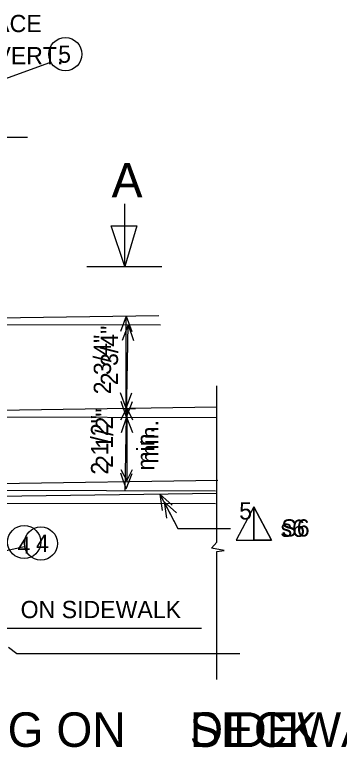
# Model space of a CAD drawing. Extents: x 1509.2 to 1521.3, y 1506 to 1514.6.
# Drawn here: x 1511.957 to 1512.741, y 1509.298 to 1511.067 of the extents above; entities that cross this region are included whole.
import ezdxf

# ---------------------------------------------------------------- set-up
doc = ezdxf.new("R2010")
doc.units = 0
for name, color, linetype in [('Level 2', 7, 'Continuous'), ('Level 3', 7, 'Continuous'), ('Level 4', 7, 'Continuous'), ('Level 60', 7, 'Continuous')]:
    doc.layers.add(name, color=color, linetype=linetype)

msp = doc.modelspace()

# ---------------------------------------------------------------- linework, layer by layer
at = {"layer": 'Level 2'}
msp.add_line((1512.5343, 1509.8786), (1512.5343, 1509.7983), dxfattribs=at)
for points in [[(1512.4919, 1509.7983), (1512.5767, 1509.7983), (1512.5343, 1509.8786)], [(1512.5343, 1509.8786), (1512.5767, 1509.7983), (1512.5343, 1509.7983)]]:
    msp.add_lwpolyline(points, close=True, dxfattribs=at)
at = {"layer": 'Level 3'}
for p, q in [((1512.2236, 1510.4586), (1512.2236, 1510.6102)), ((1512.2236, 1510.4586), (1512.1906, 1510.5574)), ((1512.1906, 1510.5574), (1512.2523, 1510.5574)), ((1512.2523, 1510.5574), (1512.2236, 1510.4586)), ((1512.1313, 1510.4586), (1512.3125, 1510.4586)), ((1511.7425, 1510.3321), (1512.3049, 1510.3405)), ((1512.2268, 1510.3393), (1512.2131, 1510.3018)), ((1512.2268, 1510.3393), (1512.2131, 1510.3018)), ((1512.2268, 1510.1165), (1512.2268, 1510.3393)), ((1512.2268, 1510.3393), (1512.2404, 1510.3018)), ((1512.2268, 1510.3393), (1512.2404, 1510.3018)), ((1512.4451, 1509.7934), (1512.4451, 1510.1704)), ((1512.2268, 1510.1165), (1512.2131, 1510.1541)), ((1512.2268, 1510.1165), (1512.2404, 1510.1541)), ((1510.9693, 1510.0976), (1512.445, 1510.1198)), ((1512.2186, 1510.1157), (1512.2486, 1510.1157)), ((1512.2278, 1510.1165), (1512.2278, 1509.9395)), ((1511.0337, 1509.9216), (1512.4477, 1509.9428)), ((1511.0322, 1509.8914), (1512.445, 1509.9114)), ((1512.308, 1509.9093), (1512.3512, 1509.826)), ((1512.308, 1509.9093), (1512.3132, 1509.8697)), ((1512.308, 1509.9093), (1512.3374, 1509.8823)), ((1512.3512, 1509.826), (1512.4771, 1509.826)), ((1511.7863, 1509.7384), (1511.98, 1509.7828)), ((1512.4325, 1509.7783), (1512.4451, 1509.7934)), ((1512.4627, 1509.7733), (1512.4325, 1509.7783)), ((1512.4451, 1509.7708), (1512.4627, 1509.7733)), ((1512.4451, 1509.4616), (1512.4451, 1509.7708)), ((1511.9423, 1509.5395), (1511.9623, 1509.5244)), ((1511.9623, 1509.5244), (1512.5003, 1509.5244))]:
    msp.add_line(p, q, dxfattribs=at)
for points in [[(1512.2138, 1510.0887), (1512.2278, 1510.1164), (1512.2417, 1510.0887)], [(1512.2138, 1509.9688), (1512.2278, 1509.941), (1512.2417, 1509.9688)]]:
    msp.add_lwpolyline(points, dxfattribs=at)
msp.add_circle((1512.0208, 1509.79), 0.04, dxfattribs=at)
at = {"layer": 'Level 4'}
for p, q in [((1511.8799, 1510.8929), (1512.042, 1510.9512)), ((1511.3357, 1510.7714), (1511.9883, 1510.7714)), ((1512.2236, 1510.4586), (1512.2236, 1510.6102)), ((1512.2236, 1510.4586), (1512.1906, 1510.5574)), ((1512.1906, 1510.5574), (1512.2523, 1510.5574)), ((1512.2523, 1510.5574), (1512.2236, 1510.4586)), ((1512.1313, 1510.4586), (1512.3125, 1510.4586)), ((1511.7468, 1510.3191), (1512.3093, 1510.3178)), ((1512.2312, 1510.3179), (1512.2168, 1510.2805)), ((1512.2312, 1510.3179), (1512.2168, 1510.2805)), ((1512.2242, 1509.9182), (1512.2312, 1510.3179)), ((1512.2273, 1510.0951), (1512.2312, 1510.3179)), ((1512.2312, 1510.3179), (1512.2442, 1510.2801)), ((1512.2312, 1510.3179), (1512.2442, 1510.2801)), ((1512.4451, 1509.7934), (1512.4451, 1510.1704)), ((1512.2273, 1510.0951), (1512.2143, 1510.1329)), ((1512.2273, 1510.0951), (1512.2143, 1510.1329)), ((1512.2273, 1510.0951), (1512.2416, 1510.1325)), ((1512.2273, 1510.0951), (1512.2416, 1510.1325)), ((1510.9697, 1510.0983), (1512.4456, 1510.0946)), ((1512.2273, 1510.095), (1512.2141, 1510.0573)), ((1512.2273, 1510.095), (1512.2414, 1510.0577)), ((1512.2268, 1509.9219), (1512.2138, 1509.9598)), ((1512.2268, 1509.9219), (1512.2411, 1509.9593)), ((1511.0634, 1509.9207), (1512.4419, 1509.9173)), ((1511.0614, 1509.8897), (1512.4419, 1509.8863)), ((1512.3182, 1509.8903), (1512.3241, 1509.8508)), ((1512.3182, 1509.8903), (1512.348, 1509.8638)), ((1512.3196, 1509.8869), (1512.3512, 1509.826)), ((1512.3512, 1509.826), (1512.4778, 1509.826)), ((1512.4325, 1509.7783), (1512.4451, 1509.7934)), ((1512.4627, 1509.7733), (1512.4325, 1509.7783)), ((1512.4451, 1509.7708), (1512.4627, 1509.7733)), ((1512.4451, 1509.4616), (1512.4451, 1509.7708)), ((1512.4083, 1509.585), (1511.9123, 1509.585)), ((1511.9623, 1509.5244), (1512.5003, 1509.5244))]:
    msp.add_line(p, q, dxfattribs=at)
for centre in [(1512.0798, 1510.9716), (1511.9805, 1509.7934)]:
    msp.add_circle(centre, 0.04, dxfattribs=at)

# ---------------------------------------------------------------- texts
at = {"layer": 'Level 2'}
msp.add_text('SECTION THRU RAILING ON', height=0.083334, rotation=0, dxfattribs=at).set_placement((1510.7146, 1509.2988))
at = {"layer": 'Level 3'}
for s, height, rotation, p in [('THIS FACE', 0.04167, 0, (1511.7316, 1511.0248)), ('TO BE VERT.', 0.041667, 0, (1511.7283, 1510.9471)), ('A', 0.0833, 0, (1512.1911, 1510.6255)), ('2 3/4"', 0.04167, 90, (1512.2068, 1510.1722)), ('2 1/2"', 0.04167, 90, (1512.1947, 1509.9723)), ('min.', 0.04167, 90, (1512.3043, 1509.9828)), ('4', 0.0417, 0, (1512.0089, 1509.7696))]:
    msp.add_text(s, height=height, rotation=rotation, dxfattribs=at).set_placement(p)
for s, height, p in [('S6  ', 0.04167, (1512.6008, 1509.8067)), (' DECK', 0.08333, (1512.3488, 1509.2988))]:
    msp.add_text(s, height=height, dxfattribs=at).set_placement(p)
at = {"layer": 'Level 4'}
for s, height, rotation, p in [('5', 0.0417, 0, (1512.0623, 1510.9508)), ('A', 0.0833, 0, (1512.1918, 1510.6255)), ('2 3/4"', 0.04167, 90, (1512.1899, 1510.1503)), ('2 1/2"', 0.04167, 90, (1512.1832, 1509.9562)), ('min.', 0.04167, 90, (1512.294, 1509.9659)), ('4', 0.0417, 0, (1511.9645, 1509.765))]:
    msp.add_text(s, height=height, rotation=rotation, dxfattribs=at).set_placement(p)
for s, height, p in [('s6  ', 0.04167, (1512.5989, 1509.8059)), ('ON SIDEWALK', 0.041667, (1511.9718, 1509.6097)), (' SIDEWALK', 0.08333, (1512.3488, 1509.2988))]:
    msp.add_text(s, height=height, dxfattribs=at).set_placement(p)
at = {"layer": 'Level 60'}
msp.add_text('5', height=0.0417, dxfattribs=at).set_placement((1512.4991, 1509.8478))

doc.saveas('drawing.dxf')
